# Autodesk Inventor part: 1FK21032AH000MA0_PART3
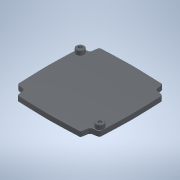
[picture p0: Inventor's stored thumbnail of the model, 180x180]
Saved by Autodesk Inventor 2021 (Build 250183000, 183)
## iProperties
Created: 2025-04
Part Number: 1FK21032AH000MA0_PART3
Material: Generic
Catalog Web Link: www.3dfindit.com
Description: -Servo synchronous motor
Document SubType Name: Modeling
Designer: psAdmin
Mass: 11.8521 g
Surface Area: 76.041 cm^2
Volume: 11.8521 cm^3
Density: 1 g/cm^3
Appearance: PSOLRGB-38-46-56
Category: PARTsolutions
Title: 1FK21032AH000MA0_PART3
Author: Cadenas PARTsolutions
Comments: Servo synchronous motor
Sending System: PARTsolutions
Preprocessor: ST-DEVELOPER v19.3
PSOL_IDENT_0: {$CADENAS_DATA/23d-libs/siemens_ag/_cat_/45/10/1fk21032ah000ma0.prj},213 {VTYP=3D},{NB=1FK21032AH000
PSOL_IDENT_1: MA0_PART3},{LINA=1FK21032AH000MA0_PART3},{NN=1FK21032AH000MA0_PART3},{NOPRJ=TRUE},{DATE=19.08.2025 1
PSOL_IDENT_2: 4:00:35},{GEOMDATE=30.07.2025 02:02:03},{VERSION=},{LINEID=10},{WBVAR=},{WBNUMERIC=}  {NB=1FK21032AH
PSOL_IDENT_3: 000MA0_PART3},{LINA=1FK21032AH000MA0_PART3},{KT=DUMMY},{PREVIEW=../../../_pool_/14/8e/p_d211_xx_0042
PSOL_IDENT_4: 6j.png},{DESCSHORT=SIMOTICS S-1FK2 HD, SINAMICS S210 3AC 400V-480V, 0.59 Nm, 4500 rpm},{DESCLONG=SIM
PSOL_IDENT_5: OTICS S-1FK2 HD servo motor M0=0.64 Nm; PN = 0.28 kW at nN=4500 rpm (380-480 V); PN = 0.167 kW at nN=
PSOL_IDENT_6: 2500 rpm (200-240 V); degree of protection IP64; cylindrical shaft D14 x 30 mm; absolute encoder 22-
PSOL_IDENT_7: bit + 12-bit multiturn (encoder AM22DQC); with OCC interface; plug size M17, rotatable; SIMOTICS S-1
PSOL_IDENT_8: FK2 servomotorfor a wide range of uses in industrial environments. SIMOTICS S‑1FK2 servomotors are c
PSOL_IDENT_9: ompact synchronous motors with a high dynamic performance that set themselves apart as a result of t
PSOL_IDENT_10: heir high power density, degree of protection and overload capability. The motors are available in t
PSOL_IDENT_11: wo variants: as High Dynamic variant (highest dynamic performance as a result of the low intrinsic m
PSOL_IDENT_12: oment of inertia for applications demanding a high dynamic performance with low moved masses) - and
PSOL_IDENT_13: as Compact variant (precise and stable closed-loop control for medium up to large moved masses as a
PSOL_IDENT_14: result of a medium intrinsic moment of inertia). SIMOTICSS‑1FK2 servomotors fully exploit their stre
PSOL_IDENT_15: ngths in a system with the SINAMICSS210 frequency converter and simple connection using the one cabl
PSOL_IDENT_16: e connection (OCC). Advantages include the short control and positioning times, fast and precise cor
PSOL_IDENT_17: rection of disturbing quantities as well as stable control with a high dynamic performance. The serv
PSOL_IDENT_18: o motors can be configured to address a wide range of requirements. For example with and without hol
PSOL_IDENT_19: ding brake, IP64 or IP65 degree of protection, singleturn or multiturn absolute encoders - to name j
PSOL_IDENT_20: ust a few. Further, the servomotors are available in different shaft heights extending from 20 to 10
PSOL_IDENT_21: 0. A shaft sealing ring is available to achieve an IP65 degree of protection and for subsequent moun
PSOL_IDENT_22: ting at the motor or as spare part. SIMOTICS - the optimum motor for each and every motion control a
PSOL_IDENT_23: pplication.},{INTNO=195125335004},{SUPPLIERALTNO=1FK2103-2AH00-0MA0},{MANUID=1FK21032AH000MA0},{MANU
PSOL_IDENT_24: NAME=Siemens},{MANUTYPEDESC=SYNCHRONOUS MOTOR 1FK2 HD 0,64 NM},{AAU732=SIMOTICS},{AAO057=S-1FK2},{AA
PSOL_IDENT_25: U734=SIMOTICS S-1FK2 HD servo motor M0=0.64 Nm; PN = 0.28 kW at nN=4500 rpm (380-480 V); PN = 0.167
PSOL_IDENT_26: kW at nN=2500 rpm (200-240 V); degree of protection IP64; cylindrical shaft D14 x 30 mm; absolute en
PSOL_IDENT_27: coder 22-bit + 12-bit multiturn (encoder AM22DQC); with OCC interface; plug size M17, rotatable;},{A
PSOL_IDENT_28: AW338=SYNCHRONOUS MOTOR 1FK2 HD 0,64 NM},{AAO742=SIMOTICS},{AAO663=4034106444624},{NOCUPEROU=1},{PRI
PSOL_IDENT_29: CEQUANTITY=1},{QUANTITYMIN=1},{QUANTITYINT=1},{CTN=85015100},{COO=RO},{AAO676=1FK2103-2AH00-0MA0},{A
PSOL_IDENT_30: AO677=Siemens AG},{ORDERUNIT=C62},{CONTENTUNIT=C62}
NB: 1FK21032AH000MA0_PART3
NT: Servo synchronous motor
NBSYN: $MANUID._PART3
LINA: 1FK21032AH000MA0_PART3
CATALOG: SIEMENS
PREVIEW: ../../../_pool_/14/8e/p_d211_xx_00426j.png
DESCSHORT: SIMOTICS S-1FK2 HD, SINAMICS S210 3AC 400V-480V, 0.59 Nm, 4500 rpm
DESCLONG: SIMOTICS S-1FK2 HD servo motor M0=0.64 Nm; PN = 0.28 kW at nN=4500 rpm (380-480 V); PN = 0.167 kW at nN=2500 rpm (200-240 V); degree of protection IP64; cylindr
INTNO: 195125335004
SUPPLIERALTNO: 1FK2103-2AH00-0MA0
MANUID: 1FK21032AH000MA0
MANUNAME: Siemens
MANUTYPEDESC: SYNCHRONOUS MOTOR 1FK2 HD 0,64 NM
AAU732: SIMOTICS
AAO057: S-1FK2
AAU734: SIMOTICS S-1FK2 HD servo motor M0=0.64 Nm; PN = 0.28 kW at nN=4500 rpm (380-480 V); PN = 0.167 kW at nN=2500 rpm (200-240 V); degree of protection IP64; cylindr
AAW338: SYNCHRONOUS MOTOR 1FK2 HD 0,64 NM
AAO742: SIMOTICS
AAO663: 4034106444624.0
NOCUPEROU: 1
PRICEQUANTITY: 1
QUANTITYMIN: 1
QUANTITYINT: 1
CTN: 85015100
COO: RO
ARTICLENO: 1FK21032AH000MA0_PART3
BOMINFO: 1FK21032AH000MA0_PART3
CREATOR: CADENAS GmbH
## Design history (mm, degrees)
feature "2025_04_17_15_00_20_0635"
body "Solid1"
